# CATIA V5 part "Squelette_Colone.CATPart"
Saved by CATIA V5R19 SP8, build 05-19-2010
Part number: Squelette_Colone
Bounding box of the stored display mesh (mm): x 0 to 0, y 0 to 300, z 0 to 1250
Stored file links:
  G:\EU_thinkMotion\CFAO_2010\MMS_groupe2\MMS_groupe2\OK\nrosalie\nrosalie_cfao_support_d_arme_legere_final\Squelette_Colone.CATPart
  G:\EU_thinkMotion\CFAO_2010\MMS_groupe2\MMS_groupe2\OK\nrosalie\nrosalie_cfao_support_d_arme_legere_final\nrosalie_Support_d_arme_legere.CATProduct
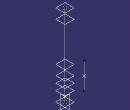
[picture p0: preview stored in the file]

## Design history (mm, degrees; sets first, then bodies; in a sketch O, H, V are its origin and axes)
External parameters (linked from other documents)
  External.Hauteur_plan_horizontal_milieu_liaison_pivot_siege = 250 mm
  External.Hauteur_du_siege = 600 mm
  External.Longueur_liaison_pivot_colonne_systeme = 150 mm
  External.Hauteur_colonne = 1250 mm
  External.Longueur_liaison_pivot_siege = 200 mm
  External.Distance_axe_colone_axe_siege = 300 mm
  External.Hauteur_colonne.1 = 1250 mm
  External.Hauteur_de_l_assise_du_siege = 500 mm
Set1
  Plane1 "Plan_median_horizontal_liaison_pivot_siege": type Offset, RefPlane xy-plane, Offset 250 {= External.Hauteur_plan_horizontal_milieu_liaison_pivot_siege}
  Plane2 "Plan_hauteur_assise_du_siege": type Offset, RefPlane xy-plane, Offset 500 {= External.Hauteur_de_l_assise_du_siege}
  Plane3 "Plan_limite_superieur_colonne": type OffsetPt, RefPlane xy-plane, RefPoint Point1
  Plane4 "Plan_limite_inferieur_liaison_pivot_colone_systeme": type Offset, RefPlane Plane3, Offset 150 {= External.Longueur_liaison_pivot_colonne_systeme}, reversed
  Point1 "Centre_plan_limite_superieur_colonne": (0, 0, 1250 {= External.Hauteur_colonne.1})
  Point2 "Origine": (0, 0, 0)
  Line1 "Axe_vertical_colonne": type PtPt, FirstPoint Point2, SecondPoint Point1
  Plane5 "Plan_superieur_liaison_pivot_siege": type Offset, RefPlane Plane1, Offset 100 {= External.Longueur_liaison_pivot_siege/2}
  Plane6 "Plan_inferieur_liaison_pivot_siege": type Offset, RefPlane Plane1, Offset 100 {= External.Longueur_liaison_pivot_siege/2}, reversed
  Point3 "Centre_axe_siege": type OnPlane, Support Plane2, H 0, V 300 {= External.Distance_axe_colone_axe_siege}, Direction (1, 0, 0)
  Line2 "Axe_siege": type Normal, RefPoint Point3, RefSkin Plane2, Start -200, End 200
Body1 (main body)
